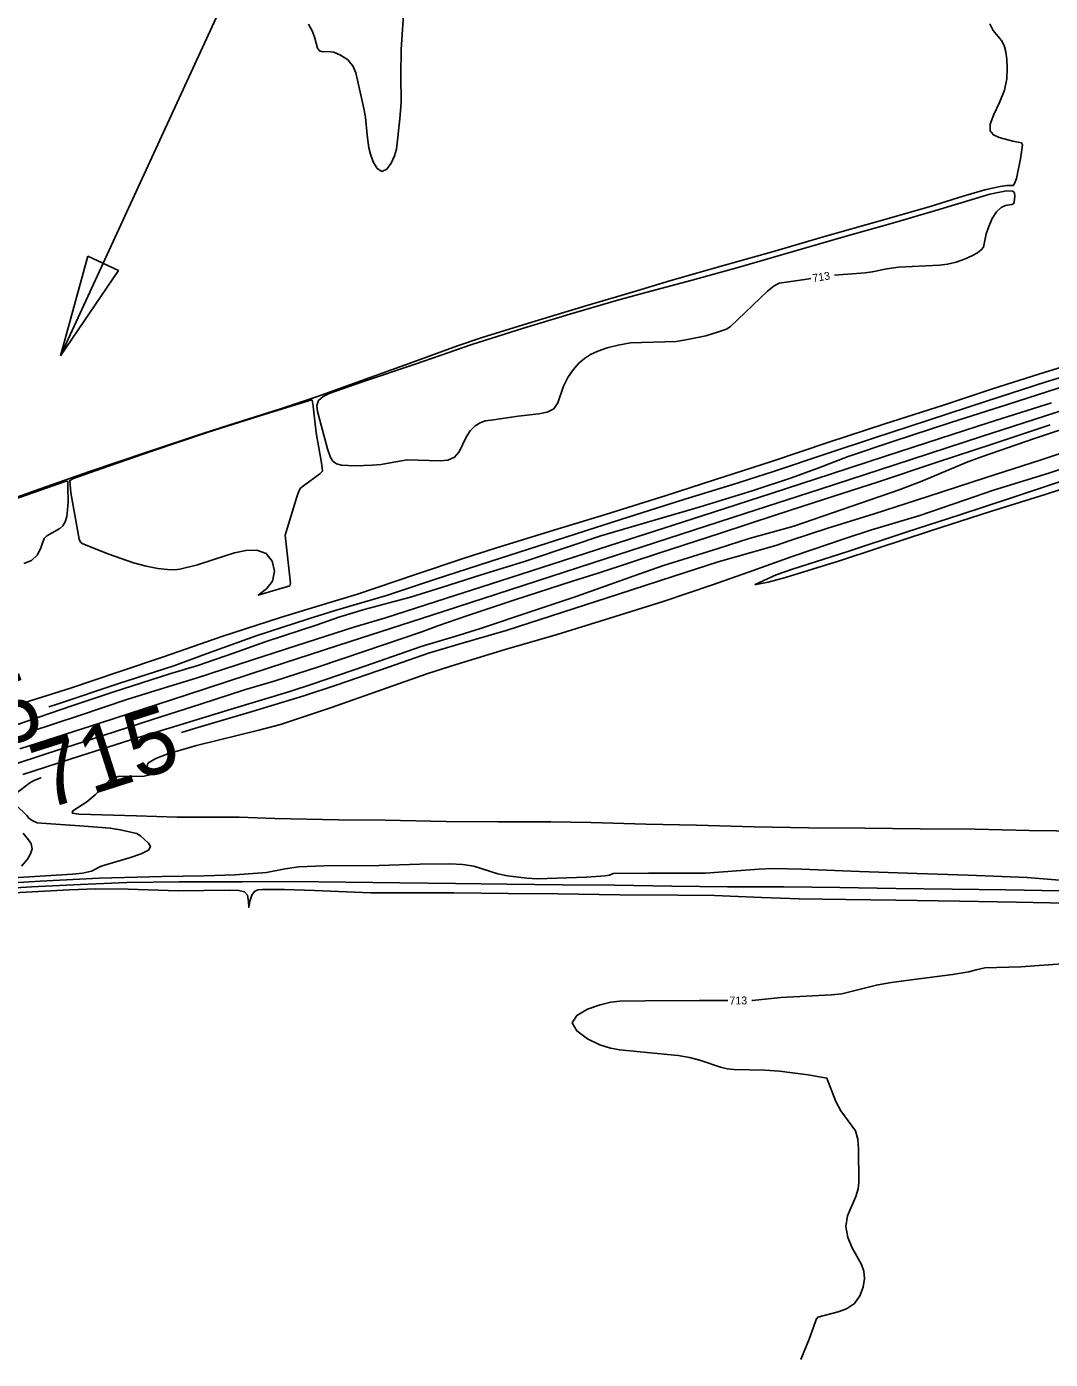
# Model space of a CAD drawing. Extents: x -468548933 to 3387700, y -306089263 to 1207014.
# Drawn here: x 1838071 to 1838588, y 535983 to 536656 of the extents above; entities that cross this region are included whole.
import ezdxf

# ---------------------------------------------------------------- set-up
doc = ezdxf.new("R2010")
doc.units = 0
for name, color, linetype in [('DT_X_Contour_Minor', 7, 'Continuous'), ('Level 14', 7, 'Continuous'), ('Level 19', 7, 'Continuous'), ('Level 40', 7, 'Continuous')]:
    doc.layers.add(name, color=color, linetype=linetype)

msp = doc.modelspace()

# ---------------------------------------------------------------- linework, layer by layer
at = {"layer": 'DT_X_Contour_Minor'}
for points in [[(1838261.4, 536667.43), (1838259.9, 536644.81), (1838259.74, 536631.67), (1838259.84, 536618.12), (1838259.27, 536609.84), (1838257.62, 536594.5), (1838256.62, 536591.16), (1838254.89, 536587.47), (1838252.64, 536584.4), (1838250.19, 536583.23), (1838247.85, 536584.76), (1838245.83, 536588.11), (1838244.34, 536591.91), (1838243.49, 536595.15), (1838242.8, 536601.6), (1838241.85, 536610.61), (1838241.1, 536615.1), (1838237.81, 536629.3), (1838237.01, 536633.08), (1838235.44, 536636.65), (1838232.73, 536639.72), (1838229.31, 536642.04), (1838225.8, 536643.41), (1838222.73, 536643.77), (1838220.3, 536643.74), (1838218.62, 536644.09), (1838217.68, 536645.43), (1838216.35, 536650.61), (1838215.02, 536653.97), (1838213.05, 536657.63)], [(1838557.44, 536657.86), (1838559.11, 536654.36), (1838563.4, 536649.43), (1838564.76, 536646.8), (1838565.54, 536643.66), (1838566, 536639.87), (1838566.3, 536635.32), (1838566.06, 536630.08), (1838564.8, 536624.24), (1838562.31, 536618.02), (1838559.51, 536612.05), (1838557.64, 536607.12), (1838557.63, 536603.76), (1838559.28, 536601.68), (1838562.12, 536600.35), (1838569.13, 536598.57), (1838573.5, 536597.63), (1838573.98, 536596.6), (1838572.92, 536589.52), (1838570.89, 536579.66), (1838570, 536577.12), (1838569.29, 536576.17), (1838567.93, 536576.05), (1838566.04, 536576.11), (1838562.73, 536575.64), (1838554.87, 536573.98), (1838544.03, 536570.65), (1838526.79, 536565.3), (1838501.37, 536558.13), (1838473.84, 536550.3), (1838448.2, 536542.83), (1838422.88, 536535.61), (1838396.19, 536528.16), (1838377.37, 536522.42), (1838353.28, 536515.25), (1838325.89, 536507.06), (1838300.8, 536499.26), (1838288.4, 536495.12), (1838265.85, 536486.83), (1838240, 536477.53), (1838217.59, 536469.53), (1838198.91, 536463.26), (1838172.73, 536455.03), (1838159.68, 536450.83), (1838131.43, 536441.4), (1838102.43, 536431.56), (1838077.52, 536422.75), (1838053.63, 536414.43)], [(1838279.55, 536490.19), (1838295.59, 536495.73), (1838321.81, 536504), (1838345.23, 536511.04), (1838368.83, 536518), (1838383.66, 536522.03), (1838406.98, 536528.33), (1838430.73, 536534.89), (1838457.99, 536542.78), (1838483.72, 536550.25), (1838509.38, 536557.47), (1838532.43, 536564.08), (1838557.55, 536571.73), (1838565.95, 536573.38), (1838568.96, 536573.23), (1838569.53, 536572.97), (1838569.95, 536572.2), (1838570.11, 536570.78), (1838569.79, 536567.69), (1838569.35, 536566.91), (1838568.57, 536566.59), (1838565.43, 536565.99), (1838563.19, 536564.96), (1838560.85, 536562.86), (1838558.7, 536559.47), (1838556.91, 536555.44), (1838555.68, 536551.66), (1838554.21, 536545.02), (1838553.1, 536543.52), (1838551.22, 536542.05), (1838548.42, 536540.52), (1838544.68, 536538.92), (1838540.4, 536537.44), (1838536.08, 536536.35), (1838532.09, 536535.82), (1838511.25, 536534.83), (1838505.38, 536534.02), (1838498.05, 536532.48), (1838494.45, 536532.03), (1838478.94, 536530.83)], [(1838467.07, 536529.11), (1838464.03, 536528.61), (1838450.96, 536526.7), (1838448.44, 536525.44), (1838445.14, 536522.66), (1838426.35, 536504.86), (1838424.39, 536503.57), (1838420.28, 536502.09), (1838413.85, 536500.21), (1838403.75, 536498.2), (1838398.94, 536497.36), (1838375.83, 536496.59), (1838369.54, 536495.5), (1838363.97, 536494.02), (1838359.3, 536492.37), (1838355.6, 536490.69), (1838352.54, 536488.75), (1838349.72, 536486.26), (1838346.83, 536482.98), (1838344.11, 536479.06), (1838341.91, 536474.74), (1838339.05, 536466.25), (1838337.04, 536463.2), (1838333.79, 536461.52), (1838329.47, 536460.75), (1838318.99, 536459.51), (1838305.38, 536457.53), (1838302.46, 536457.11), (1838299.88, 536456.25), (1838297.32, 536454.61), (1838294.87, 536452.17), (1838292.75, 536449), (1838289.24, 536441.61), (1838286.88, 536438.77), (1838283.56, 536437.3), (1838279.56, 536436.9), (1838263.03, 536437.45), (1838254.38, 536435.97), (1838249.87, 536435.19), (1838245.3, 536434.75), (1838236.63, 536434.53), (1838229.71, 536434.81), (1838227.2, 536435.53), (1838225.42, 536436.86), (1838224.2, 536438.68), (1838222.67, 536442.98), (1838217.58, 536461.97), (1838217.25, 536464.96), (1838218.09, 536467.5), (1838220.43, 536469.51), (1838223.54, 536471.02), (1838240.92, 536477.06), (1838266.98, 536485.85), (1838279.55, 536490.19)], [(1838056, 536310.71), (1838075.15, 536316.53), (1838092.79, 536322.05), (1838117.28, 536330.33), (1838139.77, 536337.87), (1838169.26, 536348.27), (1838198.92, 536357.8), (1838216.62, 536363.12), (1838237.91, 536369.52), (1838267.23, 536379.51), (1838291.68, 536387.78), (1838307.68, 536392.93), (1838337.04, 536402.01), (1838363.26, 536409.94), (1838393.92, 536419.51), (1838418.34, 536427.43), (1838447.64, 536436.83), (1838476.14, 536446.37), (1838504.47, 536455.71), (1838533.99, 536465.09), (1838558.8, 536473.32), (1838582.69, 536480.96), (1838611.75, 536489.81)], [(1838081.8, 536312.61), (1838086.04, 536314.01), (1838117.14, 536324.41), (1838145, 536333.46), (1838161.85, 536339.57), (1838186.6, 536348.47), (1838213.13, 536357.2), (1838226.64, 536361.32), (1838252.51, 536368.97), (1838276.81, 536376.94), (1838304.91, 536386.14), (1838333.7, 536395.34), (1838362.57, 536404.65), (1838374.72, 536408.45), (1838402.75, 536417.48), (1838426.99, 536424.93), (1838448.08, 536431.6), (1838475.27, 536440.71), (1838498.73, 536448.44), (1838526.43, 536457.48), (1838556.27, 536467.31), (1838585.94, 536476.91), (1838609.95, 536484.19)], [(1838065.96, 536303.68), (1838093.51, 536313.24), (1838114.63, 536320.28), (1838142.96, 536329.31), (1838157.22, 536333.54), (1838175.11, 536339.81), (1838191.76, 536345.68), (1838217.45, 536354.14), (1838228.33, 536357.9), (1838241.29, 536361.86), (1838256.34, 536365.83), (1838264.56, 536368.02), (1838280.37, 536373.01), (1838300.39, 536379.37), (1838322.34, 536386.05), (1838346.33, 536394.26), (1838360.92, 536399.1), (1838389.67, 536407.53), (1838411.02, 536413.74), (1838437.34, 536421.9), (1838457.2, 536428.33), (1838471.08, 536433.52), (1838485.92, 536439.11), (1838508.52, 536446.7), (1838537.83, 536456.42), (1838566.41, 536465.51), (1838596.66, 536475.21)], [(1838072.17, 536300.04), (1838097.84, 536308.41), (1838121.21, 536316.34), (1838140.31, 536322.35), (1838156.36, 536327.08), (1838184.34, 536336.17), (1838207.13, 536343.64), (1838236.04, 536352.9), (1838251.92, 536357.62), (1838282.27, 536367.35), (1838310.14, 536376.27), (1838336.31, 536384.68), (1838364.93, 536394.02), (1838392.71, 536402.97), (1838417.86, 536411.02), (1838447.02, 536420.39), (1838477.41, 536430.41), (1838504.71, 536439.3), (1838532.23, 536448.31), (1838557.1, 536456.36), (1838588.57, 536466.34)], [(1838203.72, 536373.86), (1838187.66, 536369.11), (1838191.89, 536372.34), (1838194.9, 536376.18), (1838195.89, 536381.21), (1838194.7, 536386.32), (1838191.62, 536390.18), (1838187, 536391.82), (1838181.46, 536391.65), (1838175.68, 536390.42), (1838165.3, 536387.15), (1838156.97, 536384.47), (1838148.06, 536382.29), (1838145.3, 536381.94), (1838141.74, 536381.99), (1838136.93, 536382.57), (1838131.09, 536383.72), (1838124.61, 536385.43), (1838111.61, 536390.01), (1838098.61, 536395.15), (1838097.78, 536395.88), (1838097.17, 536397.42), (1838092.94, 536420.83), (1838092.36, 536427.12), (1838094.24, 536428), (1838108.07, 536432.98), (1838133.82, 536441.92), (1838161.9, 536451.3), (1838190.72, 536460.38), (1838214.76, 536467.87), (1838214.99, 536467.56), (1838215.39, 536464.55), (1838216.96, 536451.14), (1838219.57, 536435.98), (1838220.19, 536431.79), (1838218.8, 536430.43), (1838210.52, 536424.32), (1838209.1, 536423.22), (1838208.32, 536421.97), (1838207.3, 536419.32), (1838201.35, 536399.45), (1838203.93, 536375.23), (1838203.72, 536373.86)], [(1838587.9, 536455.11), (1838558.62, 536445.41), (1838530.87, 536436.24), (1838501.13, 536426.39), (1838473.89, 536417.57), (1838449.39, 536409.61), (1838420.85, 536400.28), (1838390.74, 536390.57), (1838359.96, 536380.45), (1838346.54, 536376.1), (1838317.4, 536366.69), (1838293.04, 536358.73), (1838278.38, 536353.53), (1838270.39, 536350.57), (1838241.55, 536340.87), (1838218.07, 536332.93), (1838196.3, 536325.89), (1838180.77, 536321.21), (1838158.57, 536314.01), (1838134.18, 536306.32), (1838109.87, 536298.33), (1838080.43, 536288.87), (1838062.62, 536283.07)], [(1838609.1, 536457.8), (1838579.97, 536448.33), (1838553.69, 536439.21), (1838546.29, 536436.53), (1838523.1, 536426.78), (1838511.64, 536422.37), (1838487.73, 536414.08), (1838458.43, 536404.01), (1838447.53, 536400.89), (1838435.82, 536397.74), (1838420.2, 536392.69), (1838392.07, 536383.9), (1838375.25, 536378.07), (1838348.32, 536368.35), (1838325.69, 536360.85), (1838299.94, 536352.18), (1838289.23, 536348.87), (1838270.11, 536343.12), (1838241.54, 536333.18), (1838215.43, 536324.26), (1838203.56, 536320.45), (1838174.04, 536311.48), (1838146.52, 536303.1), (1838126.02, 536296.76), (1838097.77, 536287.83), (1838068.73, 536278.43)], [(1838617.06, 536440.47), (1838587.29, 536430.67), (1838559.4, 536422.1), (1838544.68, 536417.07), (1838522.14, 536409.35), (1838497.09, 536401.92), (1838484.78, 536397.95), (1838457.56, 536388.65), (1838435.55, 536380.72), (1838417.37, 536374.38), (1838392.28, 536365.95), (1838365.36, 536357.41), (1838338.75, 536349.27), (1838312.55, 536341.6), (1838287.67, 536334.06), (1838273.41, 536329.55), (1838249.97, 536321.18), (1838224.62, 536312.32), (1838198.96, 536303.8), (1838188.01, 536300.83), (1838156.48, 536293.07), (1838142.01, 536288.89), (1838135.83, 536286.63), (1838131.81, 536284.17), (1838131.38, 536281.78), (1838132.62, 536279.73), (1838132.8, 536278.29), (1838129.93, 536277.64), (1838116.93, 536277.54), (1838114.46, 536276.84), (1838112.04, 536275.08), (1838105.2, 536268.26), (1838101.05, 536264.67), (1838093.99, 536260.05), (1838093.67, 536258.92), (1838096.91, 536258.39), (1838126.18, 536257.67), (1838146.65, 536256.96), (1838177.97, 536256.89), (1838196.01, 536256.29), (1838228.18, 536255.65), (1838251.88, 536255.34), (1838282.62, 536254.8), (1838309.01, 536254.58), (1838335.5, 536254.56), (1838355.83, 536254.19), (1838383.51, 536253.37), (1838409.15, 536252.84), (1838438.29, 536252.11), (1838465.87, 536251.59), (1838494.29, 536251.37), (1838522.24, 536251.04), (1838550.07, 536250.8), (1838577.43, 536250.22), (1838604.68, 536249.9)], [(1838607.89, 536445.55), (1838583.38, 536437.48), (1838555.69, 536428.59), (1838526.11, 536418.9), (1838499.06, 536410.26), (1838475.54, 536402.98), (1838456.55, 536396.74), (1838449.28, 536394.26), (1838438.06, 536390.95), (1838420.16, 536385.86), (1838397.19, 536378.49), (1838369.71, 536369.61), (1838341.6, 536360.43), (1838312.97, 536351.23), (1838288.99, 536344.41), (1838273.76, 536339.76), (1838253.48, 536332.76), (1838227.11, 536323.54), (1838210.67, 536318.17), (1838182.93, 536309.82), (1838157.14, 536302.18), (1838148.89, 536299.67)], [(1838064.11, 536417.44), (1838090.12, 536426.57), (1838091.37, 536426.75), (1838091.5, 536423.49), (1838091.53, 536416.19), (1838091.34, 536412.17), (1838090.89, 536408.77), (1838090.12, 536406.08), (1838088.94, 536404.09), (1838087.34, 536402.72), (1838080.83, 536399.05), (1838079.48, 536397.73), (1838078.62, 536395.3), (1838077.62, 536392.56), (1838075.86, 536389.38), (1838073.09, 536386.65), (1838069.19, 536385.03)], [(1838592.63, 536426.36), (1838568.47, 536418.35), (1838542.23, 536409.74), (1838515.13, 536400.94), (1838485.14, 536390.99), (1838457.71, 536382.28), (1838449.47, 536379.42), (1838438.8, 536374.54), (1838439.42, 536374.45), (1838445.43, 536375.71), (1838454.2, 536377.95), (1838481.52, 536386.5), (1838500.43, 536392.7), (1838527.56, 536401.65), (1838557.78, 536411.31), (1838585.52, 536419.95), (1838606.75, 536426.84)], [(1838077.98, 536276.91), (1838077.84, 536276.87), (1838074.74, 536275.63), (1838072.71, 536274.53), (1838065.86, 536269.36)], [(1838065.35, 536262.99), (1838070.62, 536257.68), (1838071.82, 536256.31), (1838073.78, 536255.04), (1838075.91, 536254.11), (1838078.08, 536253.82), (1838099.6, 536252.45), (1838112.88, 536251.38), (1838117.88, 536250.47), (1838126.3, 536248.61), (1838128.1, 536247.44), (1838132.27, 536243.74), (1838133.22, 536242.05), (1838132.19, 536240.22), (1838128.42, 536238.35), (1838123.02, 536236.57), (1838108.3, 536232.2), (1838103.31, 536229.7), (1838098.9, 536228.63), (1838093.75, 536228.07), (1838063.81, 536226.34)], [(1838068.8, 536248.83), (1838071.61, 536245.54), (1838072.88, 536243.43), (1838073.35, 536240.97), (1838072.57, 536238.32), (1838070.98, 536235.76), (1838067.98, 536232.22)], [(1838603.01, 536224.29), (1838576.39, 536226.45), (1838546.51, 536227.54), (1838520.79, 536228.39), (1838491.58, 536229.47), (1838462.28, 536230.67), (1838448.01, 536230.9), (1838440.77, 536230.64), (1838413.68, 536228.57), (1838384.87, 536228.61), (1838367.06, 536228.42), (1838365.22, 536227.67), (1838362.99, 536227.23), (1838353.68, 536226.57), (1838328.74, 536225.69), (1838323.38, 536226.13), (1838313.73, 536227.22), (1838308.7, 536228.22), (1838296.69, 536232.22), (1838291.14, 536232.99), (1838284.47, 536233.34), (1838269.41, 536233.17), (1838248.7, 536232.52), (1838220.83, 536232.37), (1838208.26, 536231.81), (1838201.21, 536230.85), (1838191.79, 536228.89), (1838176.07, 536227.7), (1838160.42, 536227.28), (1838139.13, 536226.96), (1838107.27, 536226.06), (1838077.38, 536224.49), (1838049.64, 536222.84)], [(1838593.11, 536219.65), (1838565.56, 536220.12), (1838538.37, 536220.46), (1838509.93, 536220.94), (1838481.66, 536221.3), (1838453.26, 536221.66), (1838424.92, 536221.75), (1838396.65, 536222.04), (1838367.87, 536222.58), (1838341.48, 536222.73), (1838313.4, 536222.99), (1838287.45, 536223.43), (1838259.17, 536223.76), (1838231.89, 536224.08), (1838204.74, 536224.41), (1838179.52, 536224.25), (1838147.64, 536224.16), (1838121.3, 536223.92), (1838097.91, 536222.94), (1838073.13, 536221.64), (1838043.13, 536219.79)], [(1838064.16, 536218.62), (1838092.03, 536220.15), (1838105.65, 536220.66), (1838121.9, 536220.49), (1838147.24, 536219.69), (1838173.16, 536219.97), (1838177.9, 536219.89), (1838180.77, 536219.21), (1838182.22, 536217.42), (1838182.69, 536214.36), (1838182.85, 536211.33), (1838183.5, 536214.41), (1838184.47, 536217.53), (1838185.73, 536219.42), (1838187.45, 536220.23), (1838189.85, 536220.43), (1838200.92, 536220.33), (1838216.08, 536219.93), (1838244.36, 536218.76), (1838255.82, 536218.62), (1838286.56, 536218.66), (1838314.03, 536218.4), (1838339.08, 536218.14), (1838370.47, 536217.63), (1838399.74, 536217.45), (1838418.37, 536217.31), (1838442.16, 536216.32), (1838461.15, 536215.61), (1838484.67, 536215.35), (1838509.92, 536215.03), (1838542.14, 536214.42), (1838570.88, 536214), (1838596.19, 536213.52)], [(1838594.05, 536182.72), (1838573.12, 536181.22), (1838554.87, 536180.73), (1838550.51, 536179.79), (1838546.91, 536178.73), (1838538.68, 536177.35), (1838512.57, 536174.09), (1838506.52, 536173.22), (1838500.1, 536172.02), (1838482.6, 536167.72), (1838477.37, 536167.07), (1838451.88, 536165.87), (1838437.56, 536164.34), (1838437.09, 536164.33)], [(1838425.09, 536164.23), (1838410.47, 536164.31), (1838383.03, 536164.11), (1838370.42, 536163.87), (1838365.91, 536163.35), (1838360.5, 536162.11), (1838354.17, 536159.87), (1838348.72, 536156.77), (1838346.37, 536153.02), (1838348.63, 536148.9), (1838354.02, 536144.98), (1838360.32, 536141.92), (1838365.77, 536140.14), (1838370.43, 536139.32), (1838394.48, 536137.05), (1838399.98, 536136.51), (1838405.64, 536135.52), (1838411.34, 536133.94), (1838421.25, 536130.6), (1838424.78, 536129.71), (1838428.02, 536129.36), (1838443.76, 536129.05), (1838451.08, 536128.56), (1838465.6, 536126.67), (1838475.14, 536124.95), (1838479.61, 536113.16), (1838482.08, 536108.52), (1838489.6, 536098.38), (1838490.74, 536094.16), (1838491.15, 536089.49), (1838491.32, 536072.19), (1838490.97, 536069.03), (1838489.82, 536065.27), (1838485.59, 536055.5), (1838484.61, 536050), (1838485.61, 536044.5), (1838487.94, 536039.3), (1838492.59, 536030.92), (1838493.81, 536027.45), (1838494.14, 536023.74), (1838493.51, 536019.41), (1838491.83, 536014.97), (1838489, 536011.15), (1838485.09, 536008.5), (1838480.75, 536006.87), (1838470.58, 536004.25), (1838469.69, 536003.09), (1838468.27, 535999.18), (1838466.11, 535993.1), (1838461.88, 535982.94)]]:
    msp.add_lwpolyline(points, dxfattribs=at)
at = {"layer": 'Level 14'}
msp.add_lwpolyline([(1838067.23, 536291.44), (1838108.15, 536304.5), (1838151.08, 536318.56), (1838193.63, 536332.5), (1838234.22, 536345.7), (1838275.4, 536358.98), (1838314.79, 536371.83), (1838356.22, 536385.31), (1838394.77, 536397.81), (1838433.7, 536410.35), (1838471.79, 536422.71), (1838509.52, 536434.92), (1838553.19, 536449.23), (1838596.01, 536463.11), (1838642.04, 536478.18), (1838684.42, 536491.95), (1838728.12, 536506.11), (1838772.46, 536520.55), (1838816.43, 536534.82), (1838850.28, 536545.75), (1838880.4, 536555.5), (1838950.35, 536578.67)], dxfattribs=at)
at = {"layer": 'Level 40'}
for p, q in [((1838359.76, 537080.5), (1838087.73, 536489.99)), ((1838087.73, 536489.99), (1838101.52, 536540.42)), ((1838101.52, 536540.42), (1838117.12, 536533.24)), ((1838117.12, 536533.24), (1838087.73, 536489.99))]:
    msp.add_line(p, q, dxfattribs=at)

# ---------------------------------------------------------------- texts
at = {"layer": 'Level 19'}
for s, height, rotation, p in [('713', 4, 9.37359, (1838468.15, 536527.26)), ('715', 33, 18.88469, (1838011.27, 536275.76)), ('715', 33, 17.72158, (1838079.89, 536260.61)), ('713', 4, 0.5615, (1838425.88, 536162.22))]:
    msp.add_text(s, height=height, rotation=rotation, dxfattribs=at).set_placement(p)

doc.saveas('drawing.dxf')
